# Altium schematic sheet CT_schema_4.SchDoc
size 357 x 214 mm
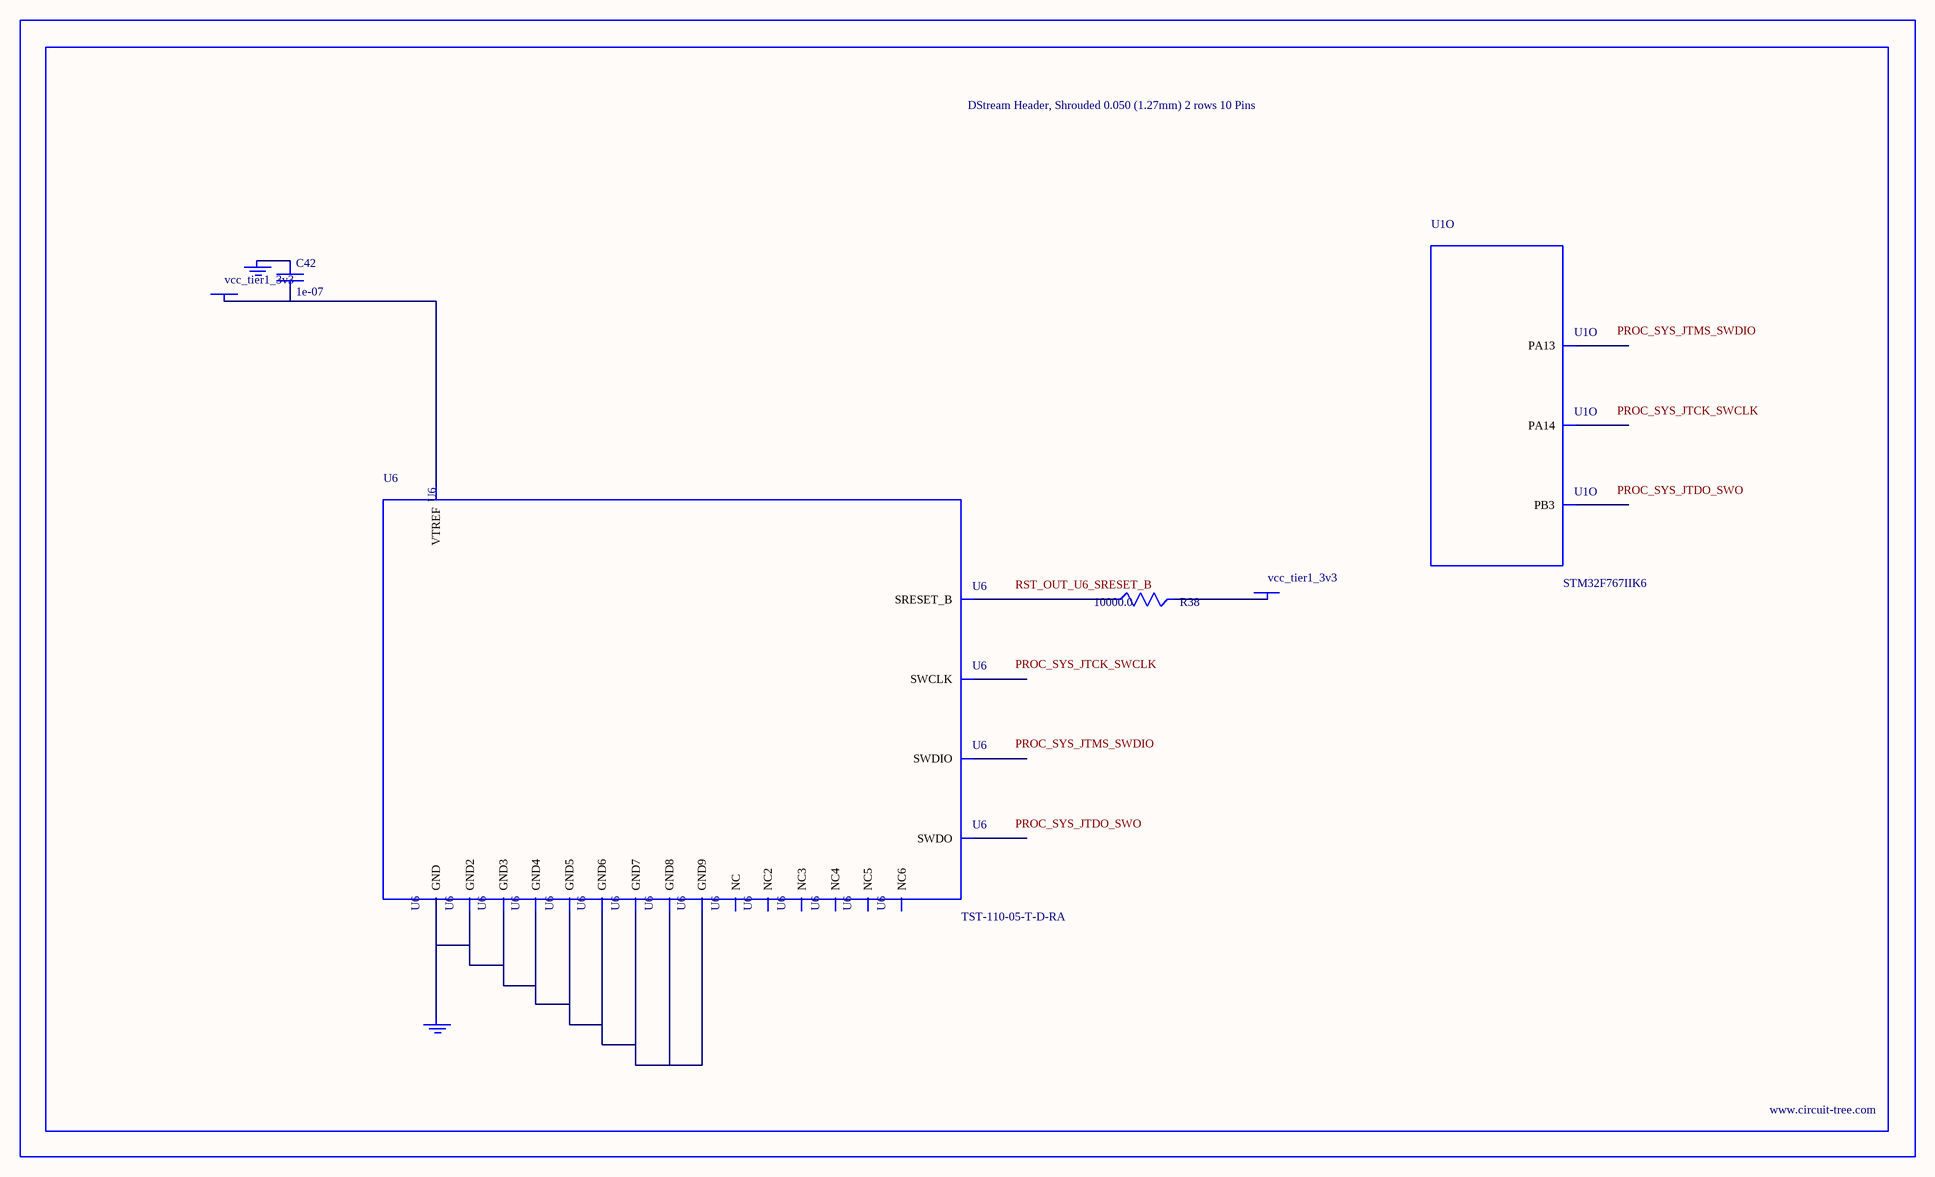
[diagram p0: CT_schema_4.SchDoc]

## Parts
BORDER3  (no value)
C42  1e-07  [C0402]
GND_INSTANCE_3_0  (no value)
GND_INSTANCE_3_1  (no value)
POWER_INSTANCE_3_0  vcc_tier1_3v3
POWER_INSTANCE_3_1  vcc_tier1_3v3
R38  10000.0  [R0603]
U1  STM32F767IIK6  [UFBGA176_25]  (part O of 17)
U6  TST-110-05-T-D-RA  [TST-110-05-T-D-RA]

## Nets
NetC42_1: C42.1 GND_INSTANCE_3_0.0(GND)
NetC42_2: C42.2 POWER_INSTANCE_3_0.0(PWR) U6.1(VTREF)
NetGND_INSTANCE_3_1_0: GND_INSTANCE_3_1.0(GND) U6.4(GND) U6.6(GND2) U6.8(GND3) U6.10(GND4) U6.12(GND5) U6.14(GND6) U6.16(GND7) U6.18(GND8) U6.20(GND9)
NetPOWER_INSTANCE_3_1_0: POWER_INSTANCE_3_1.0(PWR) R38.2
NetR38_1: R38.1 U6.15(SRESET_B)

Not connected (* = marked no-connect by the designer): U1 A10(PB3) A14(PA14) A15(PA13); U6 2(NC) 3(NC2) 5(NC3) 7(SWDIO) 9(SWCLK) 11(NC4) 13(SWDO) 17(NC5) 19(NC6)

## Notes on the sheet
- Labels drawn without touching a wire or pin: PROC_SYS_JTCK_SWCLK, PROC_SYS_JTDO_SWO, PROC_SYS_JTMS_SWDIO, RST_OUT_U6_SRESET_B

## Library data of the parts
BORDER3 = BORDER_PAGE3
C42 = C0402C104K3RACTU
GND_INSTANCE_3_0 GND_INSTANCE_3_1 = GND
POWER_INSTANCE_3_0 POWER_INSTANCE_3_1 = PWR
R38 = RC0603JR-0710KL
